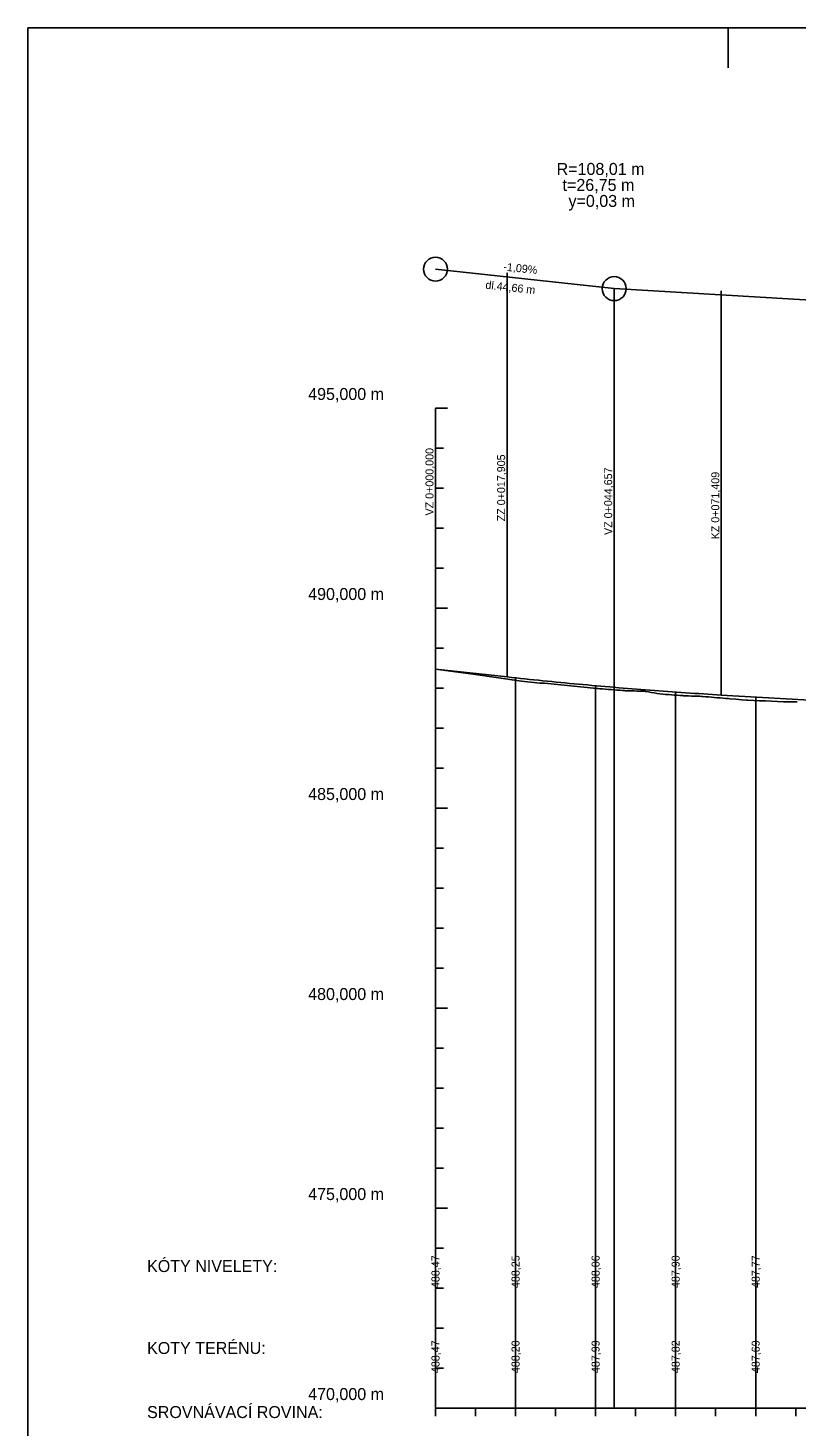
# Model space of a CAD drawing. Extents: x -632716 to -629545, y -1094726 to -1088285.
# Drawn here: x -632585.3 to -632393.4, y -1091019.7 to -1090670.2 of the extents above; entities that cross this region are included whole.
import ezdxf

# ---------------------------------------------------------------- set-up
doc = ezdxf.new("R2010")
doc.units = 0
for name, color, linetype in [('20', 7, 'Continuous'), ('56', 7, 'Continuous'), ('Default', 7, 'Continuous'), ('formát', 7, 'Continuous'), ('NIVELETA_VYSKY', 7, 'Continuous'), ('REZ_POPIS', 7, 'Continuous'), ('REZ_TENKA', 7, 'Continuous'), ('REZ_TLUSTA', 7, 'Continuous'), ('SKLONY_NIVELETA', 7, 'Continuous'), ('SKLONY_POPIS', 7, 'Continuous'), ('TECNY_NIVELETA', 7, 'Continuous'), ('TEREN_VYSKY', 7, 'Continuous'), ('VOZOVKA', 7, 'Continuous')]:
    doc.layers.add(name, color=color, linetype=linetype)

msp = doc.modelspace()

# ---------------------------------------------------------------- linework, layer by layer
at = {"layer": '20'}
for points in [[(-632483.46, -1090830.49), (-632483.46, -1090965.2), (-632483.46, -1091015.2), (-632483.46, -1090955.2)], [(-632463.46, -1090832.67), (-632463.46, -1090965.2), (-632463.46, -1091015.2), (-632463.46, -1090955.2)], [(-632443.46, -1090834.63), (-632443.46, -1090965.2), (-632443.46, -1091015.2), (-632443.46, -1090955.2)], [(-632423.46, -1090836.21), (-632423.46, -1090965.2), (-632423.46, -1091015.2), (-632423.46, -1090955.2)], [(-632403.46, -1090837.46), (-632403.46, -1090965.2), (-632403.46, -1091015.2), (-632403.46, -1090955.2)]]:
    msp.add_lwpolyline(points, dxfattribs=at)
at = {"layer": 'Default'}
for p, q in [((-632483.46, -1090830.49), (-632465.56, -1090832.44)), ((-632483.46, -1090830.49), (-632465.56, -1090832.44)), ((-632412.05, -1090836.95), (-632332.27, -1090841.69)), ((-632412.05, -1090836.95), (-632332.27, -1090841.69))]:
    msp.add_line(p, q, dxfattribs=at)
msp.add_lwpolyline([(-632465.56, -1090832.44), (-632464.44, -1090832.56), (-632463.33, -1090832.68), (-632462.21, -1090832.8), (-632461.1, -1090832.92), (-632459.99, -1090833.04), (-632458.87, -1090833.15), (-632457.76, -1090833.27), (-632456.64, -1090833.38), (-632455.53, -1090833.49), (-632454.41, -1090833.6), (-632453.3, -1090833.71), (-632452.18, -1090833.82), (-632451.07, -1090833.93), (-632449.95, -1090834.03), (-632448.84, -1090834.14), (-632447.72, -1090834.24), (-632446.61, -1090834.34), (-632445.49, -1090834.44), (-632444.38, -1090834.54), (-632443.27, -1090834.64), (-632442.15, -1090834.74), (-632441.04, -1090834.84), (-632439.92, -1090834.93), (-632437.69, -1090835.12), (-632436.58, -1090835.21), (-632435.46, -1090835.3), (-632434.35, -1090835.39), (-632433.23, -1090835.48), (-632432.12, -1090835.57), (-632431, -1090835.66), (-632429.89, -1090835.74), (-632428.77, -1090835.83), (-632427.66, -1090835.91), (-632426.55, -1090835.99), (-632425.43, -1090836.07), (-632424.32, -1090836.15), (-632423.2, -1090836.23), (-632422.09, -1090836.31), (-632420.97, -1090836.38), (-632419.86, -1090836.46), (-632418.74, -1090836.53), (-632417.63, -1090836.6), (-632416.51, -1090836.67), (-632415.4, -1090836.74), (-632414.28, -1090836.81), (-632413.17, -1090836.88), (-632412.05, -1090836.95)], dxfattribs=at)
msp.add_lwpolyline([(-632465.56, -1090832.44), (-632464.44, -1090832.56), (-632463.33, -1090832.68), (-632462.21, -1090832.8), (-632461.1, -1090832.92), (-632459.99, -1090833.04), (-632458.87, -1090833.15), (-632457.76, -1090833.27), (-632456.64, -1090833.38), (-632455.53, -1090833.49), (-632454.41, -1090833.6), (-632453.3, -1090833.71), (-632452.18, -1090833.82), (-632451.07, -1090833.93), (-632449.95, -1090834.03), (-632448.84, -1090834.14), (-632447.72, -1090834.24), (-632446.61, -1090834.34), (-632445.49, -1090834.44), (-632444.38, -1090834.54), (-632443.27, -1090834.64), (-632442.15, -1090834.74), (-632441.04, -1090834.84), (-632439.92, -1090834.93), (-632437.69, -1090835.12), (-632436.58, -1090835.21), (-632435.46, -1090835.3), (-632434.35, -1090835.39), (-632433.23, -1090835.48), (-632432.12, -1090835.57), (-632431, -1090835.66), (-632429.89, -1090835.74), (-632428.77, -1090835.83), (-632427.66, -1090835.91), (-632426.55, -1090835.99), (-632425.43, -1090836.07), (-632424.32, -1090836.15), (-632423.2, -1090836.23), (-632422.09, -1090836.31), (-632420.97, -1090836.38), (-632419.86, -1090836.46), (-632418.74, -1090836.53), (-632417.63, -1090836.6), (-632416.51, -1090836.67), (-632415.4, -1090836.74), (-632414.28, -1090836.81), (-632413.17, -1090836.88), (-632412.05, -1090836.95)], dxfattribs=at)
at = {"layer": 'formát'}
msp.add_line((-632410.3, -1090680.2), (-632410.3, -1090670.2), dxfattribs=at)
msp.add_lwpolyline([(-632585.29, -1091264.2), (-630730.3, -1091264.2), (-630730.3, -1090670.2), (-632585.29, -1090670.2)], close=True, dxfattribs=at)
at = {"layer": 'REZ_TENKA'}
for p, q in [((-632483.46, -1091015.2), (-632483.46, -1090765.2)), ((-632483.46, -1090775.2), (-632481.46, -1090775.2)), ((-632483.46, -1090785.2), (-632481.46, -1090785.2)), ((-632483.46, -1090795.2), (-632481.46, -1090795.2)), ((-632483.46, -1090805.2), (-632481.46, -1090805.2)), ((-632483.46, -1090825.2), (-632481.46, -1090825.2)), ((-632483.46, -1090835.2), (-632481.46, -1090835.2)), ((-632483.46, -1090845.2), (-632481.46, -1090845.2)), ((-632483.46, -1090855.2), (-632481.46, -1090855.2)), ((-632483.46, -1090875.2), (-632481.46, -1090875.2)), ((-632483.46, -1090885.2), (-632481.46, -1090885.2)), ((-632483.46, -1090895.2), (-632481.46, -1090895.2)), ((-632483.46, -1090905.2), (-632481.46, -1090905.2)), ((-632483.46, -1090925.2), (-632481.46, -1090925.2)), ((-632483.46, -1090935.2), (-632481.46, -1090935.2)), ((-632483.46, -1090945.2), (-632481.46, -1090945.2)), ((-632483.46, -1090955.2), (-632481.46, -1090955.2)), ((-632483.46, -1090975.2), (-632481.46, -1090975.2)), ((-632483.46, -1090985.2), (-632481.46, -1090985.2)), ((-632483.46, -1090995.2), (-632481.46, -1090995.2)), ((-632483.46, -1091005.2), (-632481.46, -1091005.2)), ((-632473.46, -1091017.2), (-632473.46, -1091015.2)), ((-632463.46, -1091017.2), (-632463.46, -1091015.2)), ((-632453.46, -1091017.2), (-632453.46, -1091015.2)), ((-632443.46, -1091017.2), (-632443.46, -1091015.2)), ((-632433.46, -1091017.2), (-632433.46, -1091015.2)), ((-632423.46, -1091017.2), (-632423.46, -1091015.2)), ((-632413.46, -1091017.2), (-632413.46, -1091015.2)), ((-632403.46, -1091017.2), (-632403.46, -1091015.2)), ((-632393.46, -1091017.2), (-632393.46, -1091015.2))]:
    msp.add_line(p, q, dxfattribs=at)
at = {"layer": 'REZ_TLUSTA'}
for p, q in [((-632483.46, -1090765.2), (-632480.46, -1090765.2)), ((-632483.46, -1090765.2), (-632480.46, -1090765.2)), ((-632483.46, -1090815.2), (-632480.46, -1090815.2)), ((-632483.46, -1090865.2), (-632480.46, -1090865.2)), ((-632483.46, -1090915.2), (-632480.46, -1090915.2)), ((-632483.46, -1090965.2), (-632480.46, -1090965.2)), ((-632483.46, -1091017.2), (-632483.46, -1091013.2)), ((-632483.46, -1091015.2), (-630763.46, -1091015.2)), ((-632483.46, -1091015.2), (-632480.46, -1091015.2))]:
    msp.add_line(p, q, dxfattribs=at)
at = {"layer": 'SKLONY_NIVELETA'}
for p, q in [((-632483.46, -1090730.49), (-632483.46, -1090730.49)), ((-632483.46, -1090730.49), (-632438.81, -1090735.36)), ((-632438.81, -1090735.36), (-632438.81, -1091015.2)), ((-632438.81, -1090735.36), (-632326.48, -1090742.03)), ((-632483.46, -1090830.49), (-632465.56, -1090832.44)), ((-632412.05, -1090836.95), (-632332.27, -1090841.69))]:
    msp.add_line(p, q, dxfattribs=at)
msp.add_lwpolyline([(-632465.56, -1090832.44), (-632464.44, -1090832.56), (-632463.33, -1090832.68), (-632462.21, -1090832.8), (-632461.1, -1090832.92), (-632459.99, -1090833.04), (-632458.87, -1090833.15), (-632457.76, -1090833.27), (-632456.64, -1090833.38), (-632455.53, -1090833.49), (-632454.41, -1090833.6), (-632453.3, -1090833.71), (-632452.18, -1090833.82), (-632451.07, -1090833.93), (-632449.95, -1090834.03), (-632448.84, -1090834.14), (-632447.72, -1090834.24), (-632446.61, -1090834.34), (-632445.49, -1090834.44), (-632444.38, -1090834.54), (-632443.27, -1090834.64), (-632442.15, -1090834.74), (-632441.04, -1090834.84), (-632439.92, -1090834.93), (-632437.69, -1090835.12), (-632436.58, -1090835.21), (-632435.46, -1090835.3), (-632434.35, -1090835.39), (-632433.23, -1090835.48), (-632432.12, -1090835.57), (-632431, -1090835.66), (-632429.89, -1090835.74), (-632428.77, -1090835.83), (-632427.66, -1090835.91), (-632426.55, -1090835.99), (-632425.43, -1090836.07), (-632424.32, -1090836.15), (-632423.2, -1090836.23), (-632422.09, -1090836.31), (-632420.97, -1090836.38), (-632419.86, -1090836.46), (-632418.74, -1090836.53), (-632417.63, -1090836.6), (-632416.51, -1090836.67), (-632415.4, -1090836.74), (-632414.28, -1090836.81), (-632413.17, -1090836.88), (-632412.05, -1090836.95)], dxfattribs=at)
for centre in [(-632483.46, -1090730.49), (-632438.81, -1090735.36)]:
    msp.add_circle(centre, 3, dxfattribs=at)
at = {"layer": 'TECNY_NIVELETA'}
for p, q in [((-632483.46, -1090730.49), (-632483.46, -1090730.49)), ((-632465.56, -1090832.44), (-632465.56, -1090731.44)), ((-632438.81, -1090735.36), (-632438.81, -1090735.36)), ((-632412.05, -1090836.95), (-632412.05, -1090735.95))]:
    msp.add_line(p, q, dxfattribs=at)
at = {"layer": 'VOZOVKA'}
msp.add_lwpolyline([(-632483.46, -1090830.51), (-632483.43, -1090830.52), (-632474.06, -1090831.74), (-632461.97, -1090833.45), (-632457.42, -1090833.95), (-632456.24, -1090834), (-632443.13, -1090835.32), (-632442.85, -1090835.35), (-632442.42, -1090835.39), (-632441.7, -1090835.44), (-632440.99, -1090835.49), (-632440.27, -1090835.55), (-632439.56, -1090835.6), (-632438.85, -1090835.66), (-632438.13, -1090835.72), (-632437.42, -1090835.77), (-632436.7, -1090835.83), (-632436.23, -1090835.86), (-632435.99, -1090835.87), (-632435.27, -1090835.89), (-632434.56, -1090835.92), (-632433.85, -1090835.94), (-632433.13, -1090835.96), (-632432.41, -1090835.98), (-632431.7, -1090836.01), (-632431.26, -1090836.02), (-632430.98, -1090836.07), (-632430.26, -1090836.19), (-632429.55, -1090836.31), (-632428.83, -1090836.42), (-632428.11, -1090836.54), (-632427.43, -1090836.65), (-632427.4, -1090836.65), (-632426.68, -1090836.71), (-632425.96, -1090836.78), (-632425.24, -1090836.84), (-632424.53, -1090836.9), (-632423.81, -1090836.95), (-632423.09, -1090837.01), (-632422.38, -1090837.06), (-632421.66, -1090837.11), (-632421.56, -1090837.12), (-632420.94, -1090837.15), (-632420.22, -1090837.17), (-632419.51, -1090837.2), (-632418.8, -1090837.22), (-632418.08, -1090837.25), (-632417.37, -1090837.27), (-632417.01, -1090837.28), (-632416.65, -1090837.31), (-632415.94, -1090837.37), (-632415.22, -1090837.44), (-632414.51, -1090837.5), (-632413.8, -1090837.56), (-632413.08, -1090837.62), (-632412.37, -1090837.68), (-632411.65, -1090837.73), (-632410.94, -1090837.79), (-632410.22, -1090837.85), (-632409.9, -1090837.88), (-632408.42, -1090838), (-632406.93, -1090838.13), (-632405.73, -1090838.23), (-632405.45, -1090838.24), (-632403.96, -1090838.31), (-632402.47, -1090838.38), (-632400.99, -1090838.44), (-632399.5, -1090838.51), (-632398.02, -1090838.58), (-632396.53, -1090838.65), (-632395.65, -1090838.69), (-632395.51, -1090838.68), (-632395.04, -1090838.68), (-632393.56, -1090838.66), (-632393.1, -1090838.65)], dxfattribs=at)

# ---------------------------------------------------------------- texts
at = {"layer": '56'}
msp.add_text('KOTY TERÉNU:', height=3, dxfattribs=at).set_placement((-632555.53, -1091001.69))
at = {"layer": 'NIVELETA_VYSKY'}
for s, p in [('488,47', (-632482.46, -1090985.2)), ('488,25', (-632462.46, -1090985.2)), ('488,06', (-632442.46, -1090985.2)), ('487,90', (-632422.46, -1090985.2)), ('487,77', (-632402.46, -1090985.2))]:
    msp.add_text(s, height=2, rotation=90, dxfattribs=at).set_placement(p)
at = {"layer": 'REZ_POPIS'}
for s, p in [('495,000 m', (-632515.28, -1090763.2)), ('495,000 m', (-632515.28, -1090763.2)), ('490,000 m', (-632515.28, -1090813.2)), ('485,000 m', (-632515.28, -1090863.2)), ('480,000 m', (-632515.28, -1090913.2)), ('475,000 m', (-632515.28, -1090963.2)), ('KÓTY NIVELETY:', (-632555.53, -1090981.2)), ('470,000 m', (-632515.28, -1091013.2)), ('SROVNÁVACÍ ROVINA:', (-632555.53, -1091017.7))]:
    msp.add_text(s, height=3, dxfattribs=at).set_placement(p)
at = {"layer": 'SKLONY_POPIS'}
for s, p in [('R=108,01 m', (-632453.2, -1090706.94)), ('t=26,75 m', (-632451.72, -1090710.94)), ('y=0,03 m', (-632450.23, -1090714.94))]:
    msp.add_text(s, height=3, dxfattribs=at).set_placement(p)
for s, rotation, p in [('-1,09%', 353.781, (-632466.57, -1090730.82)), ('dl.44,66 m', 353.781, (-632471.06, -1090735.37)), ('VZ 0+000,000', 90, (-632483.96, -1090792.07)), ('ZZ 0+017,905', 90, (-632466.06, -1090793.53)), ('VZ 0+044,657', 90, (-632439.31, -1090796.94)), ('KZ 0+071,409', 90, (-632412.55, -1090798.03))]:
    msp.add_text(s, height=2, rotation=rotation, dxfattribs=at).set_placement(p)
at = {"layer": 'TEREN_VYSKY'}
for s, p in [('488,47', (-632482.46, -1091006.46)), ('488,20', (-632462.46, -1091006.46)), ('487,99', (-632442.46, -1091006.46)), ('487,82', (-632422.46, -1091006.46)), ('487,69', (-632402.46, -1091006.46))]:
    msp.add_text(s, height=2, rotation=90, dxfattribs=at).set_placement(p)

doc.saveas('drawing.dxf')
